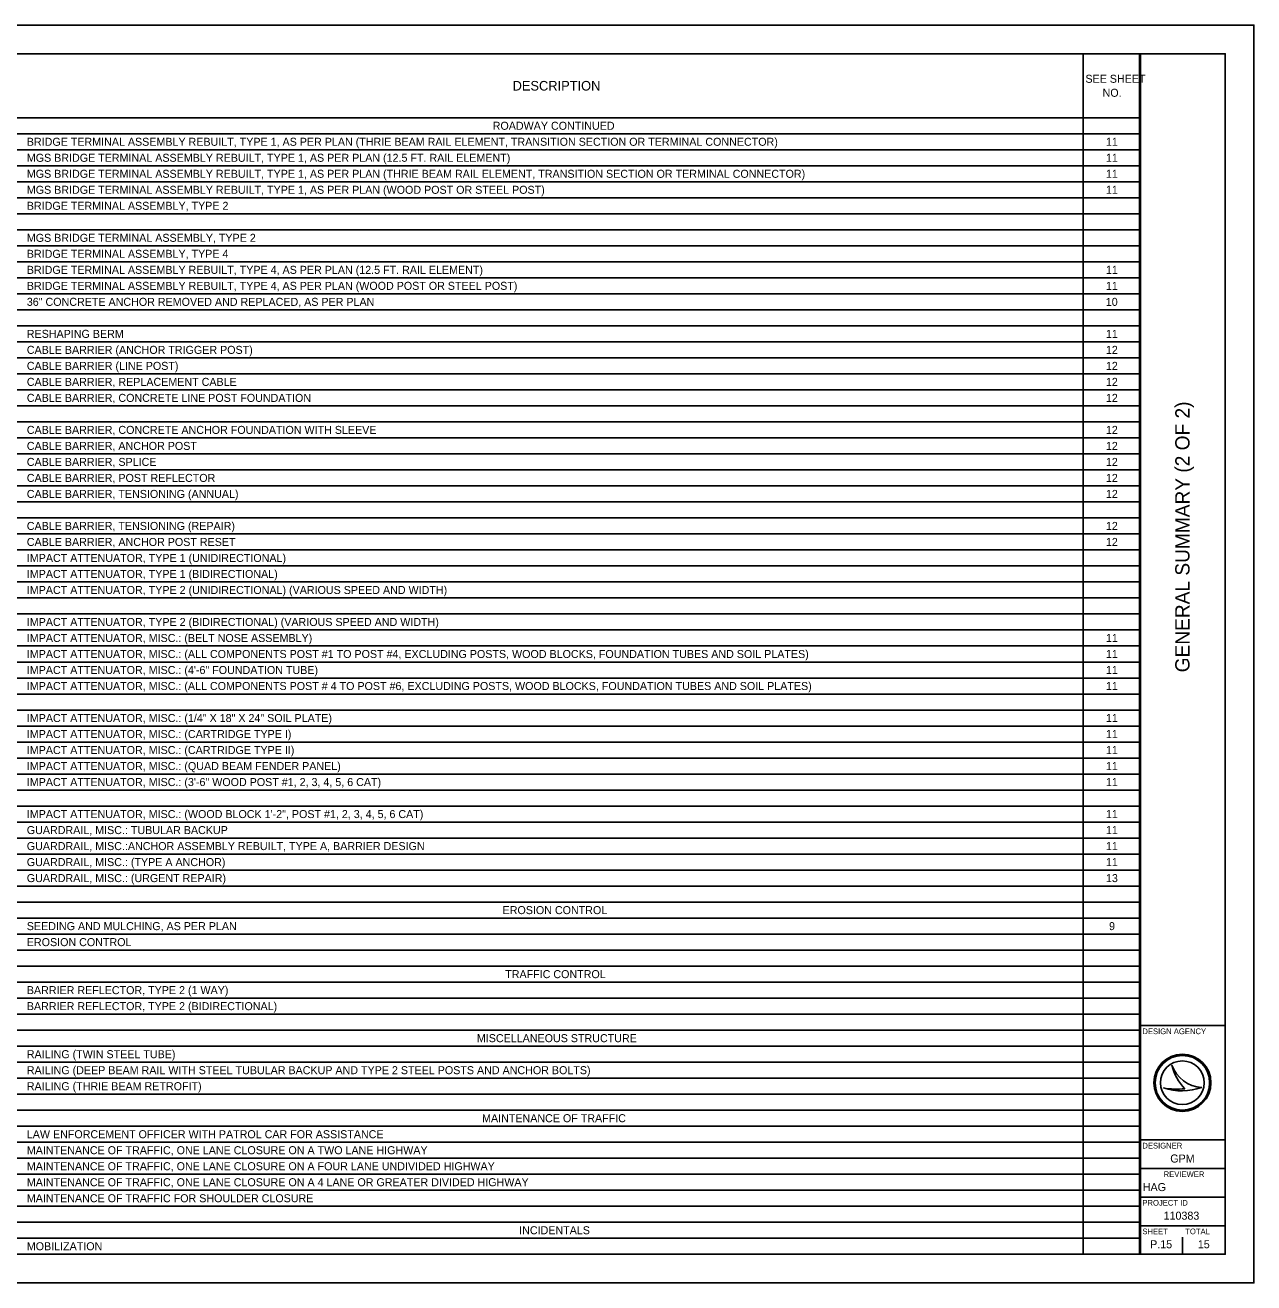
# Model space of a CAD drawing. Extents: x 0 to 34, y 0 to 22.
# Drawn here: x 12.51 to 34, y 0 to 22 of the extents above; entities that cross this region are included whole.
import ezdxf

# ---------------------------------------------------------------- set-up
doc = ezdxf.new("R2010")
doc.units = 0
for name, color, linetype in [('Default', 7, 'Continuous'), ('SH_Border', 7, 'Continuous'), ('SH_Cut_Line', 7, 'Continuous'), ('SH_Data', 7, 'Continuous')]:
    doc.layers.add(name, color=color, linetype=linetype)

msp = doc.modelspace()

# ---------------------------------------------------------------- linework, layer by layer
at = {"layer": 'Default'}
for p, q in [((1.5, 21.5), (32.02, 21.5)), ((31.015, 21.5), (31.015, 0.5)), ((32.02, 21.5), (32.02, 0.5)), ((1.5, 20.38), (32.02, 20.38)), ((1.5, 20.1), (32.02, 20.1)), ((1.5, 19.82), (32.02, 19.82)), ((1.5, 19.54), (32.02, 19.54)), ((1.5, 19.26), (32.02, 19.26)), ((1.5, 18.98), (32.02, 18.98)), ((1.5, 18.7), (32.02, 18.7)), ((1.5, 18.42), (32.02, 18.42)), ((1.5, 18.14), (32.02, 18.14)), ((1.5, 17.86), (32.02, 17.86)), ((1.5, 17.58), (32.02, 17.58)), ((1.5, 17.3), (32.02, 17.3)), ((1.5, 17.02), (32.02, 17.02)), ((1.5, 16.74), (32.02, 16.74)), ((1.5, 16.46), (32.02, 16.46)), ((1.5, 16.18), (32.02, 16.18)), ((1.5, 15.9), (32.02, 15.9)), ((1.5, 15.62), (32.02, 15.62)), ((1.5, 15.34), (32.02, 15.34)), ((1.5, 15.06), (32.02, 15.06)), ((1.5, 14.78), (32.02, 14.78)), ((1.5, 14.5), (32.02, 14.5)), ((1.5, 14.22), (32.02, 14.22)), ((1.5, 13.94), (32.02, 13.94)), ((1.5, 13.66), (32.02, 13.66)), ((1.5, 13.38), (32.02, 13.38)), ((1.5, 13.1), (32.02, 13.1)), ((1.5, 12.82), (32.02, 12.82)), ((1.5, 12.54), (32.02, 12.54)), ((1.5, 12.26), (32.02, 12.26)), ((1.5, 11.98), (32.02, 11.98)), ((1.5, 11.7), (32.02, 11.7)), ((1.5, 11.42), (32.02, 11.42)), ((1.5, 11.14), (32.02, 11.14)), ((1.5, 10.86), (32.02, 10.86)), ((1.5, 10.58), (32.02, 10.58)), ((1.5, 10.3), (32.02, 10.3)), ((1.5, 10.02), (32.02, 10.02)), ((1.5, 9.74), (32.02, 9.74)), ((1.5, 9.46), (32.02, 9.46)), ((1.5, 9.18), (32.02, 9.18)), ((1.5, 8.9), (32.02, 8.9)), ((1.5, 8.62), (32.02, 8.62)), ((1.5, 8.34), (32.02, 8.34)), ((1.5, 8.06), (32.02, 8.06)), ((1.5, 7.78), (32.02, 7.78)), ((1.5, 7.5), (32.02, 7.5)), ((1.5, 7.22), (32.02, 7.22)), ((1.5, 6.94), (32.02, 6.94)), ((1.5, 6.66), (32.02, 6.66)), ((1.5, 6.38), (32.02, 6.38)), ((1.5, 6.1), (32.02, 6.1)), ((1.5, 5.82), (32.02, 5.82)), ((1.5, 5.54), (32.02, 5.54)), ((1.5, 5.26), (32.02, 5.26)), ((1.5, 4.98), (32.02, 4.98)), ((1.5, 4.7), (32.02, 4.7)), ((1.5, 4.42), (32.02, 4.42)), ((1.5, 4.14), (32.02, 4.14)), ((1.5, 3.86), (32.02, 3.86)), ((1.5, 3.58), (32.02, 3.58)), ((1.5, 3.3), (32.02, 3.3)), ((1.5, 3.02), (32.02, 3.02)), ((1.5, 2.74), (32.02, 2.74)), ((1.5, 2.46), (32.02, 2.46)), ((1.5, 2.18), (32.02, 2.18)), ((1.5, 1.9), (32.02, 1.9)), ((1.5, 1.62), (32.02, 1.62)), ((1.5, 1.34), (32.02, 1.34)), ((1.5, 1.06), (32.02, 1.06)), ((1.5, 0.78), (32.02, 0.78)), ((1.5, 0.5), (32.02, 0.5))]:
    msp.add_line(p, q, dxfattribs=at)
at = {"layer": 'SH_Border'}
for p, q in [((32, 0.5), (32, 21.5)), ((32, 4.5), (33.5, 4.5)), ((32, 2.5), (33.5, 2.5)), ((32, 2), (33.5, 2)), ((32, 1.5), (33.5, 1.5)), ((32, 1), (33.5, 1))]:
    msp.add_line(p, q, dxfattribs=at)
msp.add_lwpolyline([(1.5, 21.5), (33.5, 21.5), (33.5, 0.5), (1.5, 0.5)], close=True, dxfattribs=at)
at = {"layer": 'SH_Cut_Line'}
msp.add_lwpolyline([(0, 0), (34, 0), (34, 22), (0, 22)], close=True, dxfattribs=at)
at = {"layer": 'SH_Data'}
for p, q in [((32.567, 3.81), (32.567, 3.81)), ((32.417, 3.41), (32.417, 3.41)), ((32.75, 3.5), (32.75, 3.5)), ((33.087, 3.419), (33.087, 3.419)), ((32.375, 0.675), (32.375, 0.675)), ((32.75, 0.5), (32.75, 0.8))]:
    msp.add_line(p, q, dxfattribs=at)
for radius in [0.5, 0.477, 0.477, 0.382]:
    msp.add_circle((32.75, 3.5), radius, dxfattribs=at)
for centre, radius, start, end in [((33.116, 3.998), 0.58, 198.9257, 198.9319), ((33.347, 3.97), 0.796, 191.6379, 191.6421), ((33.116, 3.998), 0.58, 198.9319, 267.1657), ((33.347, 3.97), 0.796, 191.6421, 226.0947), ((32.739, 4.37), 1.013, 251.4576, 290.0832), ((32.648, 4.654), 1.266, 259.4964, 259.4995), ((32.739, 4.37), 1.013, 251.4527, 251.4576), ((32.648, 4.654), 1.266, 259.4995, 276.6672)]:
    msp.add_arc(centre, radius, start, end, dxfattribs=at)

# ---------------------------------------------------------------- texts
at = {"layer": 'Default'}
for s, height, p in [('SEE SHEET ', 0.14, (31.054, 20.992)), ('DESCRIPTION', 0.168, (21.033, 20.856)), ('NO.', 0.14, (31.354, 20.747)), ('ROADWAY CONTINUED', 0.14, (20.685, 20.17)), ('BRIDGE TERMINAL ASSEMBLY REBUILT, TYPE 1, AS PER PLAN (THRIE BEAM RAIL ELEMENT, TRANSITION SECTION OR TERMINAL CONNECTOR)', 0.14, (12.535, 19.89)), ('11', 0.14, (31.412, 19.89)), ('MGS BRIDGE TERMINAL ASSEMBLY REBUILT, TYPE 1, AS PER PLAN (12.5 FT. RAIL ELEMENT)', 0.14, (12.535, 19.61)), ('11', 0.14, (31.412, 19.61)), ('MGS BRIDGE TERMINAL ASSEMBLY REBUILT, TYPE 1, AS PER PLAN (THRIE BEAM RAIL ELEMENT, TRANSITION SECTION OR TERMINAL CONNECTOR)', 0.14, (12.535, 19.33)), ('11', 0.14, (31.412, 19.33)), ('MGS BRIDGE TERMINAL ASSEMBLY REBUILT, TYPE 1, AS PER PLAN (WOOD POST OR STEEL POST)', 0.14, (12.535, 19.05)), ('11', 0.14, (31.412, 19.05)), ('BRIDGE TERMINAL ASSEMBLY, TYPE 2', 0.14, (12.535, 18.77)), ('MGS BRIDGE TERMINAL ASSEMBLY, TYPE 2', 0.14, (12.535, 18.21)), ('BRIDGE TERMINAL ASSEMBLY, TYPE 4', 0.14, (12.535, 17.93)), ('BRIDGE TERMINAL ASSEMBLY REBUILT, TYPE 4, AS PER PLAN (12.5 FT. RAIL ELEMENT)', 0.14, (12.535, 17.65)), ('11', 0.14, (31.412, 17.65)), ('BRIDGE TERMINAL ASSEMBLY REBUILT, TYPE 4, AS PER PLAN (WOOD POST OR STEEL POST)', 0.14, (12.535, 17.37)), ('11', 0.14, (31.412, 17.37)), ('36" CONCRETE ANCHOR REMOVED AND REPLACED, AS PER PLAN', 0.14, (12.535, 17.09)), ('10', 0.14, (31.41, 17.09)), ('RESHAPING BERM', 0.14, (12.535, 16.53)), ('11', 0.14, (31.412, 16.53)), ('CABLE BARRIER (ANCHOR TRIGGER POST)', 0.14, (12.535, 16.25)), ('12', 0.14, (31.412, 16.25)), ('CABLE BARRIER (LINE POST)', 0.14, (12.535, 15.97)), ('12', 0.14, (31.412, 15.97)), ('CABLE BARRIER, REPLACEMENT CABLE', 0.14, (12.535, 15.69)), ('12', 0.14, (31.412, 15.69)), ('CABLE BARRIER, CONCRETE LINE POST FOUNDATION', 0.14, (12.535, 15.41)), ('12', 0.14, (31.412, 15.41)), ('CABLE BARRIER, CONCRETE ANCHOR FOUNDATION WITH SLEEVE', 0.14, (12.535, 14.85)), ('12', 0.14, (31.412, 14.85)), ('CABLE BARRIER, ANCHOR POST', 0.14, (12.535, 14.57)), ('12', 0.14, (31.412, 14.57)), ('CABLE BARRIER, SPLICE', 0.14, (12.535, 14.29)), ('12', 0.14, (31.412, 14.29)), ('CABLE BARRIER, POST REFLECTOR', 0.14, (12.535, 14.01)), ('12', 0.14, (31.412, 14.01)), ('CABLE BARRIER, TENSIONING (ANNUAL)', 0.14, (12.535, 13.73)), ('12', 0.14, (31.412, 13.73)), ('CABLE BARRIER, TENSIONING (REPAIR)', 0.14, (12.535, 13.17)), ('12', 0.14, (31.412, 13.17)), ('CABLE BARRIER, ANCHOR POST RESET', 0.14, (12.535, 12.89)), ('12', 0.14, (31.412, 12.89)), ('IMPACT ATTENUATOR, TYPE 1 (UNIDIRECTIONAL)', 0.14, (12.535, 12.61)), ('IMPACT ATTENUATOR, TYPE 1 (BIDIRECTIONAL)', 0.14, (12.535, 12.33)), ('IMPACT ATTENUATOR, TYPE 2 (UNIDIRECTIONAL) (VARIOUS SPEED AND WIDTH)', 0.14, (12.535, 12.05)), ('IMPACT ATTENUATOR, TYPE 2 (BIDIRECTIONAL) (VARIOUS SPEED AND WIDTH)', 0.14, (12.535, 11.49)), ('IMPACT ATTENUATOR, MISC.: (BELT NOSE ASSEMBLY)', 0.14, (12.535, 11.21)), ('11', 0.14, (31.412, 11.21)), ('IMPACT ATTENUATOR, MISC.: (ALL COMPONENTS POST #1 TO POST #4, EXCLUDING POSTS, WOOD BLOCKS, FOUNDATION TUBES AND SOIL PLATES)', 0.14, (12.535, 10.93)), ('11', 0.14, (31.412, 10.93)), ('IMPACT ATTENUATOR, MISC.: (4\'-6" FOUNDATION TUBE)', 0.14, (12.535, 10.65)), ('11', 0.14, (31.412, 10.65)), ('IMPACT ATTENUATOR, MISC.: (ALL COMPONENTS POST # 4 TO POST #6, EXCLUDING POSTS, WOOD BLOCKS, FOUNDATION TUBES AND SOIL PLATES)', 0.14, (12.535, 10.37)), ('11', 0.14, (31.412, 10.37)), ('IMPACT ATTENUATOR, MISC.: (1/4" X 18" X 24" SOIL PLATE)', 0.14, (12.535, 9.81)), ('11', 0.14, (31.412, 9.81)), ('IMPACT ATTENUATOR, MISC.: (CARTRIDGE TYPE I)', 0.14, (12.535, 9.53)), ('11', 0.14, (31.412, 9.53)), ('IMPACT ATTENUATOR, MISC.: (CARTRIDGE TYPE II)', 0.14, (12.535, 9.25)), ('11', 0.14, (31.412, 9.25)), ('IMPACT ATTENUATOR, MISC.: (QUAD BEAM FENDER PANEL)', 0.14, (12.535, 8.97)), ('11', 0.14, (31.412, 8.97)), ('IMPACT ATTENUATOR, MISC.: (3\'-6" WOOD POST #1, 2, 3, 4, 5, 6 CAT)', 0.14, (12.535, 8.69)), ('11', 0.14, (31.412, 8.69)), ('IMPACT ATTENUATOR, MISC.: (WOOD BLOCK 1\'-2", POST #1, 2, 3, 4, 5, 6 CAT)', 0.14, (12.535, 8.13)), ('11', 0.14, (31.412, 8.13)), ('GUARDRAIL, MISC.: TUBULAR BACKUP', 0.14, (12.535, 7.85)), ('11', 0.14, (31.412, 7.85)), ('GUARDRAIL, MISC.:ANCHOR ASSEMBLY REBUILT, TYPE A, BARRIER DESIGN', 0.14, (12.535, 7.57)), ('11', 0.14, (31.412, 7.57)), ('GUARDRAIL, MISC.: (TYPE A ANCHOR)', 0.14, (12.535, 7.29)), ('11', 0.14, (31.412, 7.29)), ('GUARDRAIL, MISC.: (URGENT REPAIR)', 0.14, (12.535, 7.01)), ('13', 0.14, (31.413, 7.01)), ('EROSION CONTROL', 0.14, (20.858, 6.45)), ('SEEDING AND MULCHING, AS PER PLAN', 0.14, (12.535, 6.17)), ('9', 0.14, (31.467, 6.17)), ('EROSION CONTROL', 0.14, (12.535, 5.89)), ('TRAFFIC CONTROL', 0.14, (20.904, 5.33)), ('BARRIER REFLECTOR, TYPE 2 (1 WAY)', 0.14, (12.535, 5.05)), ('BARRIER REFLECTOR, TYPE 2 (BIDIRECTIONAL)', 0.14, (12.535, 4.77)), ('MISCELLANEOUS STRUCTURE', 0.14, (20.408, 4.21)), ('RAILING (TWIN STEEL TUBE)', 0.14, (12.535, 3.93)), ('RAILING (DEEP BEAM RAIL WITH STEEL TUBULAR BACKUP AND TYPE 2 STEEL POSTS AND ANCHOR BOLTS)', 0.14, (12.535, 3.65)), ('RAILING (THRIE BEAM RETROFIT)', 0.14, (12.535, 3.37)), ('MAINTENANCE OF TRAFFIC', 0.14, (20.499, 2.81)), ('LAW ENFORCEMENT OFFICER WITH PATROL CAR FOR ASSISTANCE', 0.14, (12.535, 2.53)), ('MAINTENANCE OF TRAFFIC, ONE LANE CLOSURE ON A TWO LANE HIGHWAY', 0.14, (12.535, 2.25)), ('MAINTENANCE OF TRAFFIC, ONE LANE CLOSURE ON A FOUR LANE UNDIVIDED HIGHWAY', 0.14, (12.535, 1.97)), ('MAINTENANCE OF TRAFFIC, ONE LANE CLOSURE ON A 4 LANE OR GREATER DIVIDED HIGHWAY', 0.14, (12.535, 1.69)), ('MAINTENANCE OF TRAFFIC FOR SHOULDER CLOSURE', 0.14, (12.535, 1.41)), ('INCIDENTALS', 0.14, (21.148, 0.85)), ('MOBILIZATION', 0.14, (12.535, 0.57))]:
    msp.add_text(s, height=height, dxfattribs=at).set_placement(p)
at = {"layer": 'SH_Data'}
msp.add_text('GENERAL SUMMARY (2 OF 2)', height=0.25, rotation=90, dxfattribs=at).set_placement((32.875, 10.68))
for s, height, p in [('DESIGN AGENCY', 0.1, (32.05, 4.35)), ('DESIGNER', 0.1, (32.05, 2.35)), ('GPM', 0.14, (32.538, 2.105)), ('REVIEWER', 0.1, (32.422, 1.85)), ('HAG', 0.14, (32.057, 1.605)), ('PROJECT ID', 0.1, (32.05, 1.35)), ('110383', 0.14, (32.421, 1.105)), ('SHEET', 0.1, (32.05, 0.85)), ('TOTAL', 0.1, (32.8, 0.85)), ('P.15', 0.14, (32.185, 0.605)), ('15', 0.14, (33.02, 0.605))]:
    msp.add_text(s, height=height, dxfattribs=at).set_placement(p)

doc.saveas('drawing.dxf')
